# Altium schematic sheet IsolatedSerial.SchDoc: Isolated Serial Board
size 431 x 279 mm; Date: Not shown in title block; ApprovedBy: Not shown in title block; CheckedBy: Not shown in title block; Author: Not shown in title block; CompanyName: Texas Instruments; DrawnBy: Mars Leung; Engineer: Mars Leung; Organization: Not shown in title block; Address1: Not shown in title block; Address2: Not shown in title block; Address3: Not shown in title block; Address4: Not shown in title block; DocumentNumber: 1; Revision: Use project parameter SCH_Rev; SheetNumber: 1; SheetTotal: 1; PageSetup: Record=PageOptions|CenterHorizontal=True|CenterVertical=True|PrintScale=1.00|XCorrection=1.00|YCorrection=1.00|PrintKind=0|BorderSize=5000000|LeftOffset=0|BottomOffset=0|Orientation=2|PaperLength=1000|PaperWidth=1000|Scale=100|PaperSource=15|PrintQuality=600|MediaType=1|DitherType=10|PaperKind=Letter|PrintScaleMode=1
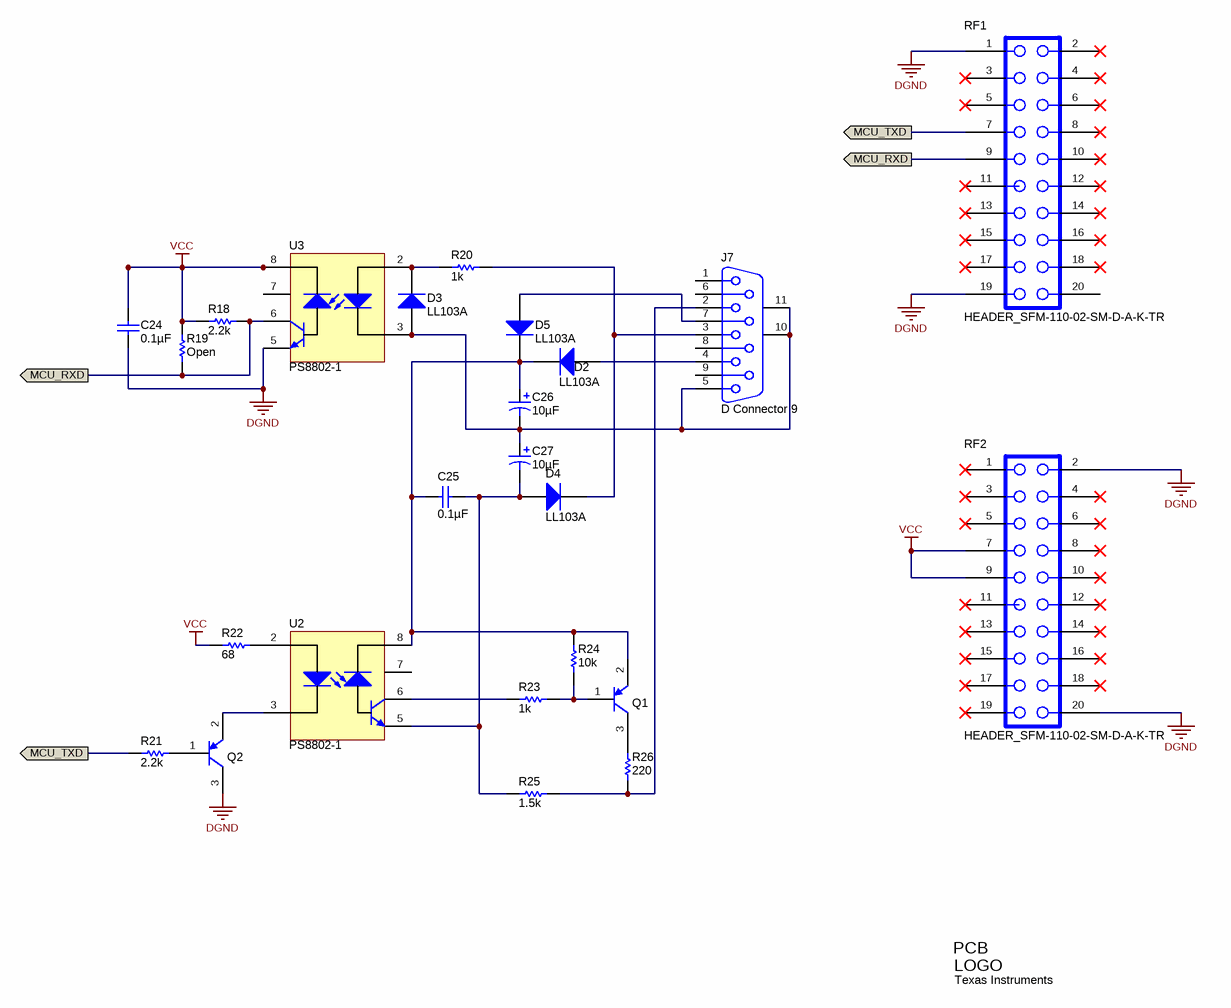
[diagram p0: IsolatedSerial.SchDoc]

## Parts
C24  ValueDisplayed: 0.1µF  [0603]  (hidden comment: C1608X7R1H104K)
C25  ValueDisplayed: 0.1µF  [0603]  (hidden comment: C1608X7R1H104K)
C26  ValueDisplayed: 10µF  [3216-18]  (hidden comment: T495A106K010ATE1K8)
C27  ValueDisplayed: 10µF  [3216-18]  (hidden comment: T495A106K010ATE1K8)
D2  LL103A  [SOD-80]
D3  LL103A  [SOD-80]
D4  LL103A  [SOD-80]
D5  LL103A  [SOD-80]
J7  D Connector 9  [DSUB9-F]
Logo6  Texas Instruments  [TI_Stacked_SolderMask_Medium]  (no BOM)
Q1  BC857C-7-F  [SOT-23]  (value not drawn)
Q2  BC857C-7-F  [SOT-23]  (value not drawn)
R18  2.2k  [0603]
R19  Open  [0603]
R20  1k  [0603]
R21  2.2k  [0603]
R22  68  [0603]
R23  1k  [0603]
R24  10k  [0603]
R25  1.5k  [0603]
R26  220  [0603]
RF1  HEADER_SFM-110-02-SM-D-A-K-TR  [HEADER_TFM-110-02-SM]
RF2  HEADER_SFM-110-02-SM-D-A-K-TR  [HEADER_TFM-110-02-SM]
U2  PS8802-1  [SO-8]
U3  PS8802-1  [SO-8]

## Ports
MCU_RXD, MCU_TXD

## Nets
DGND: C24.2 Q2.3(C) RF1.1 RF1.19 RF2.2 RF2.20 U3.5
VCC: C24.1 R18.1 R19.2 R22.1 RF2.7 RF2.9 U3.8
MCU_RXD: R18.2 R19.1 RF1.9 U3.6 ; port MCU_RXD
MCU_TXD: R21.1 RF1.7 ; port MCU_TXD
NetC25_1: C25.1 C27.2(-) D4.1(A) R25.1 U2.5
NetC25_2: C25.2 C26.1(+) D2.2(K) D5.2(K) Q1.2(E) R24.2 U2.8
NetC26_2: C26.2(-) C27.1(+) D3.1(A) J7.5 J7.10(MH1) J7.11(MH2) U3.3
NetD2_1: D2.1(A) J7.4
NetD3_2: D3.2(K) R20.1 U3.2
NetD4_2: D4.2(K) J7.3 R20.2
NetD5_1: D5.1(A) J7.7
NetJ7_2: J7.2 R25.2 R26.1
NetQ1_1: Q1.1(B) R23.2 R24.1
NetQ1_3: Q1.3(C) R26.2
NetQ2_1: Q2.1(B) R21.2
NetQ2_2: Q2.2(E) U2.3
NetR22_2: R22.2 U2.2
NetR23_1: R23.1 U2.6

Not connected (* = marked no-connect by the designer): J7 1 6 8 9; RF1 2* 3* 4* 5* 6* 8* 10* 11* 12* 13* 14* 15* 16* 17* 18* 20; RF2 1* 3* 4* 5* 6* 8* 10* 11* 12* 13* 14* 15* 16* 17* 18* 19*; U2 1 4 7; U3 1 4 7

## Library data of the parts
C24 C25 = C1608X7R1H104K: CAP, CERM, 0.1uF, 50V, +/-10%, X7R, 0603; Manufacturer: TDK; Polarized: N; CompType: Capacitor; U/M: EA; Cap_F: 0.0000001; Tolerance_%: 10; ESR_Ohm: 0.017; Value1: 0.017 ohm; VDC_V: 50; TaMin_C: -55; TaMax_C: 125
C26 C27 = T495A106K010ATE1K8: CAP, TA, 10uF, 10V, +/-10%, 1.8 ohm, SMD; Manufacturer: Kemet; Polarized: Y; CompType: Capacitor; U/M: EA; Cap_F: 0.00001; Tolerance_%: 10; Value1: 1.8 ohm; ESR_Ohm: 1.8; TaMin_C: -55; TaMax_C: 125; Cap_Case: A
D2-D5 = LL103A: Manufacturer: Used in BOM report; SymbolVersion: use current date i.e. 2008-05-20; SymbolCreator: Use LDAP id; CompType: Used in some BOM reports.  Useful for finding later.; U/M: EA, IN, or GM
J7 = D Connector 9: Receptacle Assembly, 9 Position, Right Angle; PackageDocument: O; Positions: 9
Logo6 = TI_Logo: Texas Instrument Corporate Signature; SymbolCreator: a0412235
Q1 Q2 = BC857C-7-F, Diodes Inc.: Transistor, PNP, 45V, 0.1A, SOT-23; Alternate Manufacturer: None; CompType: BJT; U/M: EA; PNP: 1; NPN: 0; Vceo_V: 45; Vcesat1_V: 0.075; Value: 0.075V; IcRated_A: 0.1; HfeMax: 600
R18 R21 = Resistor: RES, 2.2k ohm, x%, xW, [PackageReference]; Manufacturer: Used in BOM report; U/M: EA
R19 = Resistor: RES, Open ohm, x%, xW, [PackageReference]; Manufacturer: Used in BOM report; U/M: EA
R20 R23 = Resistor: RES, 1k ohm, x%, xW, [PackageReference]; Manufacturer: Used in BOM report; U/M: EA
R22 = Resistor: RES, 68 ohm, x%, xW, [PackageReference]; Manufacturer: Used in BOM report; U/M: EA
R24 = Resistor: RES, 10k ohm, x%, xW, [PackageReference]; Manufacturer: Used in BOM report; U/M: EA
R25 = Resistor: RES, 1.5k ohm, x%, xW, [PackageReference]; Manufacturer: Used in BOM report; U/M: EA
R26 = Resistor: RES, 220 ohm, x%, xW, [PackageReference]; Manufacturer: Used in BOM report; U/M: EA
RF1 RF2 = HEADER_TFM-110-02-SM-D-A-K-TR: Header, SMT 10X2 pin, Shrouded; Manufacturer: Samtec; area: 119800
U2 U3 = PS8802-1: Manufacturer: Used in BOM report; SymbolVersion: use current date i.e. 2008-05-20; SymbolCreator: Use LDAP id; CompType: Used in some BOM reports.  Useful for finding later.; U/M: EA, IN, or GM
